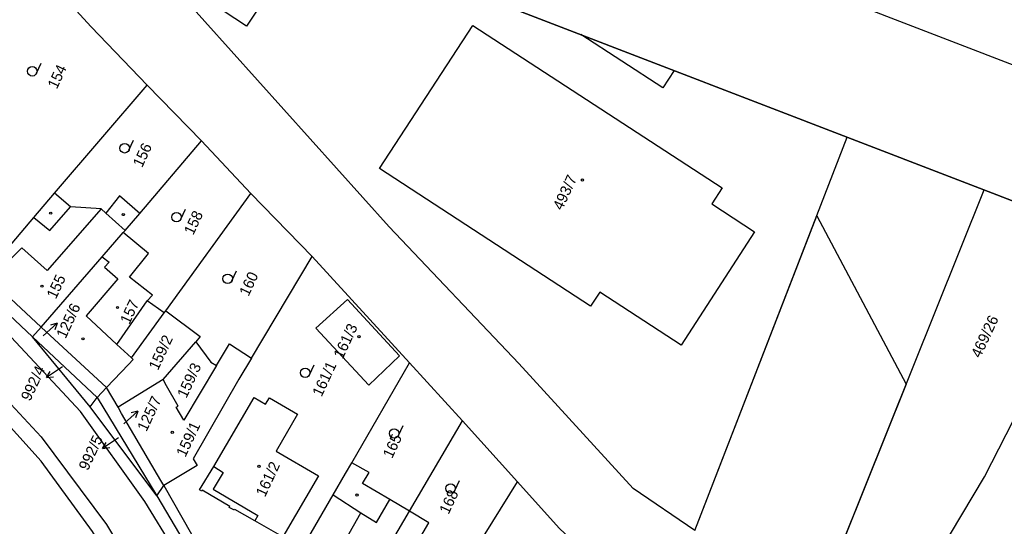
# Model space of a CAD drawing. Extents: x -755344 to -754412, y -1162670 to -1161477.
# Drawn here: x -754834.8 to -754679.8, y -1161864.3 to -1161784.6 of the extents above; entities that cross this region are included whole.
import ezdxf

# ---------------------------------------------------------------- set-up
doc = ezdxf.new("R2010")
doc.units = 0
for name, color, linetype in [('Formát', 7, 'Continuous'), ('Tabulka', 7, 'Continuous'), ('Vrstva 53', 7, 'Continuous'), ('Vrstva 55', 7, 'Continuous'), ('Vrstva 56', 7, 'Continuous'), ('Vrstva 57', 7, 'Continuous'), ('Vrstva 58', 7, 'Continuous'), ('Vrstva 59', 7, 'Continuous')]:
    doc.layers.add(name, color=color, linetype=linetype)

msp = doc.modelspace()

# ---------------------------------------------------------------- linework, layer by layer
at = {"layer": 'Formát'}
msp.add_lwpolyline([(-754488.01, -1161886.37), (-754789.71, -1162670.32), (-755344.08, -1162456.97), (-755042.37, -1161673.02)], close=True, dxfattribs=at)
for points in [[(-755344.08, -1162456.97), (-754789.71, -1162670.32), (-754488.01, -1161886.37), (-755042.37, -1161673.02)], [(-755344.08, -1162456.97), (-754789.71, -1162670.32), (-754488.01, -1161886.37), (-755042.37, -1161673.02)], [(-754789.71, -1162670.32), (-754488.01, -1161886.37), (-755042.37, -1161673.02), (-755344.08, -1162456.97)]]:
    msp.add_lwpolyline(points, dxfattribs=at)
at = {"layer": 'Tabulka'}
msp.add_lwpolyline([(-754739.34, -1161768.22), (-754678.28, -1161609.56), (-754435.63, -1161702.95), (-754496.69, -1161861.6)], close=True, dxfattribs=at)
at = {"layer": 'Vrstva 53'}
msp.add_lwpolyline([(-754728.5, -1161864.92), (-754709.3, -1161815.4), (-754695.26, -1161841.9), (-754708.18, -1161874.05)], dxfattribs=at)
at = {"layer": 'Vrstva 55'}
for p, q in [((-754829.3, -1161811.83), (-754814.71, -1161794.87)), ((-754806.13, -1161803.63), (-754814.71, -1161794.87)), ((-754815.87, -1161815.02), (-754806.13, -1161803.63)), ((-754798.38, -1161811.92), (-754806.13, -1161803.63)), ((-754811.79, -1161830.35), (-754798.38, -1161811.92)), ((-754788.76, -1161821.82), (-754798.38, -1161811.92)), ((-754708.18, -1161874.05), (-754682.98, -1161811.34)), ((-754798.29, -1161837.8), (-754788.76, -1161821.82)), ((-754773.44, -1161838.56), (-754788.76, -1161821.82)), ((-754841.56, -1161826.18), (-754832.73, -1161834.46)), ((-754812.05, -1161830.7), (-754811.79, -1161830.35)), ((-754832.73, -1161834.46), (-754831.41, -1161832.91)), ((-754831.41, -1161832.91), (-754821.08, -1161842.44)), ((-754832.73, -1161834.46), (-754822.56, -1161844)), ((-754823.68, -1161845.48), (-754832.73, -1161834.46)), ((-754812.21, -1161841.14), (-754807.07, -1161835.24)), ((-754782.47, -1161854.25), (-754773.44, -1161838.56)), ((-754765.06, -1161847.67), (-754773.44, -1161838.56)), ((-754812.21, -1161841.14), (-754819.29, -1161845.52)), ((-754822.56, -1161844), (-754821.08, -1161842.44)), ((-754819.29, -1161845.52), (-754821.08, -1161842.44)), ((-754823.68, -1161845.48), (-754822.56, -1161844)), ((-754822.56, -1161844), (-754813.2, -1161859.46)), ((-754813.2, -1161859.46), (-754823.68, -1161845.48)), ((-754773.43, -1161861.9), (-754765.06, -1161847.67)), ((-754756.43, -1161857.25), (-754765.06, -1161847.67)), ((-754765.9, -1161872.42), (-754756.43, -1161857.25)), ((-754813.2, -1161859.46), (-754812.09, -1161857.83)), ((-754813.2, -1161859.46), (-754799.29, -1161882.83))]:
    msp.add_line(p, q, dxfattribs=at)
for points in [[(-754790.69, -1161920.17), (-754823.33, -1161865.1), (-754831.37, -1161854.01), (-754842.43, -1161841.79), (-754855.01, -1161828.87), (-754953.69, -1161741.58)], [(-754789.06, -1161770.51), (-754799.07, -1161785.58), (-754806.27, -1161780.78), (-754798.32, -1161768.84), (-754804.72, -1161764.56)], [(-754814.71, -1161794.87), (-754823.5, -1161785.69), (-754833.48, -1161774.78)], [(-754728.5, -1161864.92), (-754738.21, -1161858.31), (-754756.21, -1161838.63), (-754776.63, -1161817.12), (-754813.94, -1161775.57)], [(-754763.46, -1161785.44), (-754724.19, -1161811.01), (-754725.85, -1161813.54), (-754719.1, -1161817.94), (-754730.68, -1161835.75), (-754743.45, -1161827.41), (-754744.92, -1161829.64), (-754778.14, -1161807.96), (-754763.46, -1161785.44)], [(-754728.5, -1161864.92), (-754704.52, -1161803.05)], [(-754840.24, -1161824.73), (-754832.54, -1161815.66), (-754829.3, -1161811.83)], [(-754815.87, -1161815.02), (-754819.08, -1161812.27), (-754821.23, -1161814.97), (-754821.97, -1161814.3), (-754826.77, -1161813.97), (-754829.3, -1161811.83)], [(-754818.47, -1161818.05), (-754818.18, -1161817.73), (-754815.87, -1161815.02)], [(-754831.41, -1161832.91), (-754821.79, -1161821.86), (-754818.47, -1161818.05)], [(-754812.05, -1161830.7), (-754814.68, -1161828.79), (-754813.89, -1161827.91), (-754817.47, -1161825.06), (-754814.49, -1161821.36), (-754818.47, -1161818.05)], [(-754700.13, -1161883.31), (-754693.64, -1161874.43), (-754682.9, -1161856.46), (-754669.27, -1161829.84), (-754663.3, -1161818.91)], [(-754840.24, -1161824.73), (-754839.41, -1161825.46), (-754831.41, -1161832.91)], [(-754775, -1161837.46), (-754779.84, -1161842.04), (-754788.15, -1161833.11), (-754783.2, -1161828.58), (-754775, -1161837.46)], [(-754821.08, -1161842.44), (-754817.66, -1161838.81), (-754816.89, -1161838.03), (-754817.18, -1161837.76), (-754812.05, -1161830.7)], [(-754811.79, -1161830.35), (-754806.35, -1161834.41), (-754807.07, -1161835.24)], [(-754807.07, -1161835.24), (-754804.69, -1161838.44), (-754803.79, -1161838.98)], [(-754803.79, -1161838.98), (-754801.73, -1161835.57), (-754798.29, -1161837.8)], [(-754803.79, -1161838.98), (-754808.94, -1161847.54), (-754810.15, -1161845.54), (-754809.8, -1161845.34), (-754811.66, -1161842.17), (-754812.21, -1161841.14)], [(-754798.29, -1161837.8), (-754800.26, -1161841.1), (-754807.47, -1161853.63), (-754806.84, -1161854.7), (-754812.09, -1161857.83)], [(-754797.87, -1161844.01), (-754796.07, -1161845.06), (-754795.46, -1161844.03), (-754791.02, -1161846.63), (-754794.41, -1161852.43), (-754787.75, -1161856.33), (-754793.37, -1161865.92), (-754797.77, -1161863.4), (-754800.91, -1161861.61), (-754800.98, -1161861.74), (-754801.78, -1161861.29), (-754801.71, -1161861.16), (-754806.04, -1161858.59), (-754806.12, -1161858.72), (-754806.49, -1161858.53), (-754804.23, -1161854.87), (-754797.87, -1161844.01)], [(-754812.09, -1161857.83), (-754812.54, -1161857.08), (-754818.72, -1161846.5), (-754819.29, -1161845.52)], [(-754792.56, -1161871.65), (-754785.42, -1161859.33), (-754783.47, -1161855.97), (-754782.47, -1161854.25)], [(-754773.43, -1161861.9), (-754776.54, -1161860.02), (-754780.79, -1161857.54), (-754779.75, -1161855.81), (-754782.47, -1161854.25)], [(-754745.52, -1161868.38), (-754746.92, -1161867.32), (-754749.85, -1161864.57), (-754756.43, -1161857.25)], [(-754812.09, -1161857.83), (-754803.59, -1161872.79), (-754798.49, -1161881.58)], [(-754778.04, -1161869.74), (-754776.09, -1161866.43), (-754773.43, -1161861.9)], [(-754772.01, -1161866.48), (-754770.39, -1161863.74), (-754773.43, -1161861.9)]]:
    msp.add_lwpolyline(points, dxfattribs=at)
at = {"layer": 'Vrstva 56'}
for p, q in [((-754733.53, -1161795.26), (-754746.47, -1161786.9)), ((-754731.75, -1161792.57), (-754733.53, -1161795.26)), ((-754830.01, -1161817.74), (-754826.77, -1161813.97)), ((-754832.54, -1161815.66), (-754830.01, -1161817.74)), ((-754821.97, -1161814.3), (-754830.44, -1161824.03)), ((-754821.23, -1161814.97), (-754818.18, -1161817.73)), ((-754834.41, -1161820.45), (-754839.41, -1161825.46)), ((-754830.44, -1161824.03), (-754834.41, -1161820.45)), ((-754821.79, -1161821.86), (-754820.7, -1161822.71)), ((-754820.7, -1161822.71), (-754821.4, -1161823.5)), ((-754821.4, -1161823.5), (-754819.3, -1161825.31)), ((-754819.3, -1161825.31), (-754824.33, -1161831.17)), ((-754825.18, -1161846.21), (-754843.11, -1161827)), ((-754819.49, -1161835.64), (-754814.68, -1161828.79)), ((-754824.33, -1161831.17), (-754819.49, -1161835.64)), ((-754848.39, -1161832.02), (-754831.41, -1161850.21)), ((-754819.49, -1161835.64), (-754817.18, -1161837.76)), ((-754815.09, -1161860.38), (-754825.18, -1161846.21)), ((-754831.41, -1161850.21), (-754821.11, -1161863.98)), ((-754802.72, -1161855.78), (-754804.3, -1161858.42)), ((-754804.23, -1161854.87), (-754802.72, -1161855.78)), ((-754804.3, -1161858.42), (-754797.27, -1161862.54)), ((-754806, -1161875.03), (-754815.09, -1161860.38)), ((-754785.42, -1161859.33), (-754781.07, -1161862.16)), ((-754778.59, -1161863.64), (-754776.54, -1161860.02)), ((-754784.08, -1161867.42), (-754781.07, -1161862.16)), ((-754781.07, -1161862.16), (-754778.59, -1161863.64)), ((-754797.27, -1161862.54), (-754797.77, -1161863.4)), ((-754821.11, -1161863.98), (-754807.06, -1161886.86))]:
    msp.add_line(p, q, dxfattribs=at)
at = {"layer": 'Vrstva 57'}
for p, q in [((-754831.07, -1161834.3), (-754828.86, -1161832.28)), ((-754828.86, -1161832.28), (-754829.93, -1161832.59)), ((-754828.86, -1161832.28), (-754829.26, -1161833.33)), ((-754828.05, -1161839.19), (-754830.55, -1161840.86)), ((-754830.55, -1161840.86), (-754829.99, -1161839.88)), ((-754830.55, -1161840.86), (-754829.44, -1161840.72)), ((-754818.37, -1161848.15), (-754816.15, -1161846.13)), ((-754816.15, -1161846.13), (-754817.23, -1161846.43)), ((-754816.15, -1161846.13), (-754816.55, -1161847.17)), ((-754819.22, -1161850.36), (-754821.71, -1161852.02)), ((-754821.71, -1161852.02), (-754821.16, -1161851.05)), ((-754821.71, -1161852.02), (-754820.6, -1161851.88))]:
    msp.add_line(p, q, dxfattribs=at)
at = {"layer": 'Vrstva 58'}
for p, q in [((-754832.11, -1161792.98), (-754831.37, -1161791.4)), ((-754817.57, -1161805.09), (-754816.83, -1161803.51)), ((-754809.41, -1161815.93), (-754808.67, -1161814.35)), ((-754801.36, -1161825.63), (-754800.62, -1161824.05)), ((-754789.16, -1161840.43), (-754788.42, -1161838.84)), ((-754775.16, -1161849.96), (-754774.42, -1161848.38)), ((-754766.28, -1161858.62), (-754765.54, -1161857.04))]:
    msp.add_line(p, q, dxfattribs=at)
for centre in [(-754832.79, -1161792.67), (-754818.25, -1161804.78), (-754810.09, -1161815.62), (-754802.04, -1161825.32), (-754789.84, -1161840.11), (-754775.84, -1161849.65), (-754766.96, -1161858.31)]:
    msp.add_circle(centre, 0.75, dxfattribs=at)
at = {"layer": 'Vrstva 59'}
for centre in [(-754746.2, -1161809.79), (-754829.89, -1161814.99), (-754818.46, -1161815.21), (-754831.27, -1161826.48), (-754819.37, -1161829.83), (-754781.37, -1161834.43), (-754824.82, -1161834.77), (-754810.76, -1161849.48), (-754797.12, -1161854.84), (-754781.67, -1161859.35)]:
    msp.add_circle(centre, 0.175, dxfattribs=at)

# ---------------------------------------------------------------- texts
at = {"layer": 'Vrstva 57'}
for s, p in [('154', (-754828.92, -1161795.58)), ('156', (-754815.5, -1161807.92)), ('493/7', (-754749.4, -1161814.66)), ('158', (-754807.46, -1161818.56)), ('155', (-754829.07, -1161828.62)), ('160', (-754798.76, -1161828.18)), ('125/6', (-754827.55, -1161834.85)), ('157', (-754817.51, -1161832.59)), ('469/26', (-754683.6, -1161837.9)), ('161/3', (-754783.93, -1161838.04)), ('159/2', (-754813.01, -1161839.84)), ('159/3', (-754808.54, -1161844.22)), ('161/1', (-754787.26, -1161844)), ('992/4', (-754833.12, -1161844.68)), ('125/7', (-754814.81, -1161849.46)), ('159/1', (-754808.69, -1161853.49)), ('165', (-754776.16, -1161853.7)), ('992/5', (-754824.03, -1161855.61)), ('161/2', (-754796.15, -1161859.76)), ('168', (-754767.27, -1161862.48))]:
    msp.add_text(s, height=1.7, rotation=65, dxfattribs=at).set_placement(p)

doc.saveas('drawing.dxf')
